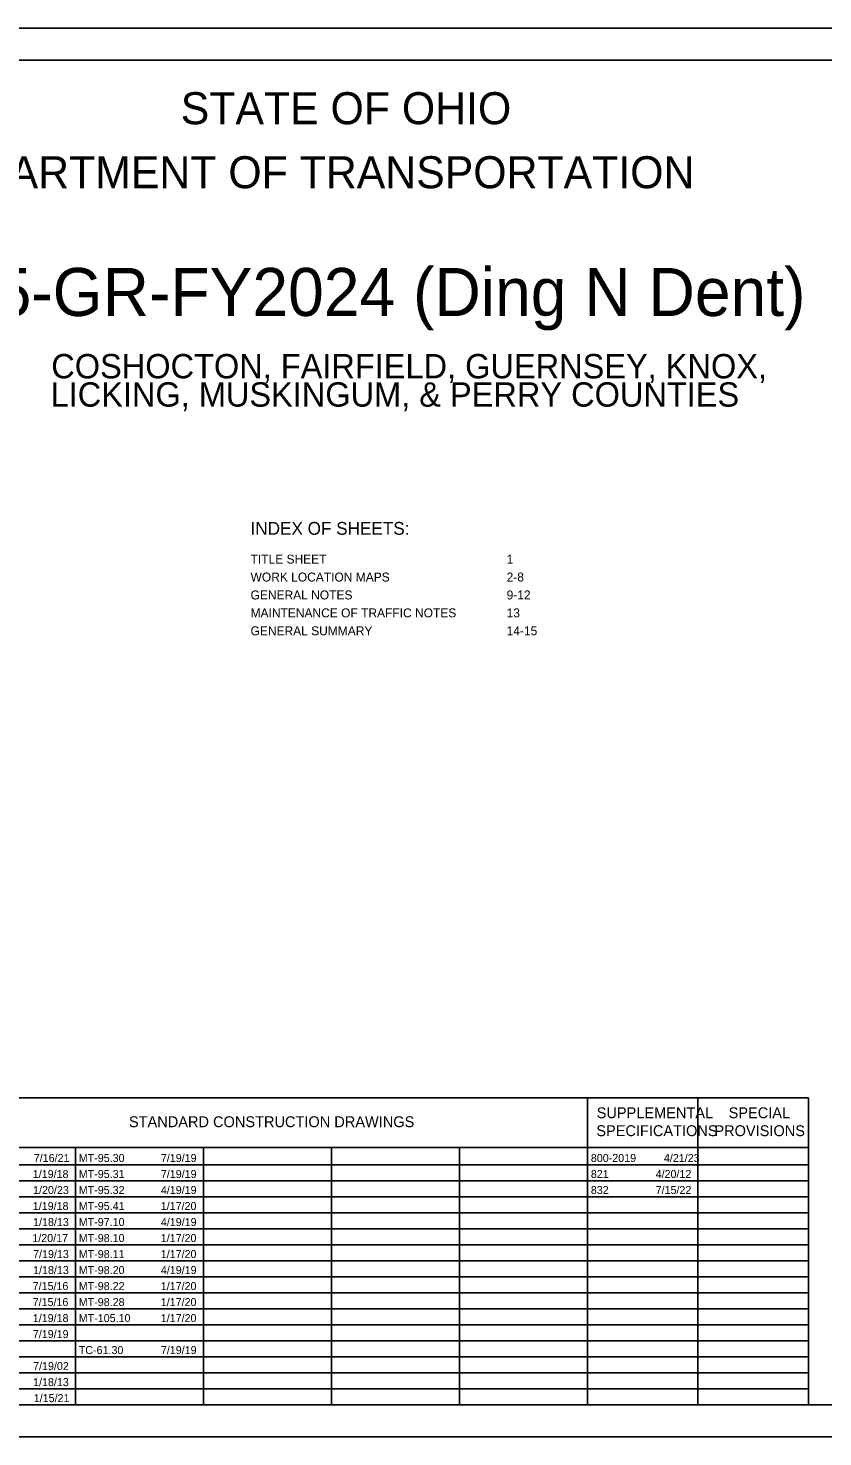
# Model space of a CAD drawing. Extents: x 0 to 34, y 0 to 22.
# Drawn here: x 11.41 to 23.83, y 0 to 22 of the extents above; entities that cross this region are included whole.
import ezdxf

# ---------------------------------------------------------------- set-up
doc = ezdxf.new("R2010")
doc.units = 0
for name, color, linetype in [('Default', 7, 'Continuous'), ('SH_Border', 7, 'Continuous'), ('SH_Cut_Line', 7, 'Continuous'), ('SH_Data', 7, 'Continuous'), ('SH_Text', 7, 'Continuous')]:
    doc.layers.add(name, color=color, linetype=linetype)

msp = doc.modelspace()

# ---------------------------------------------------------------- linework, layer by layer
at = {"layer": 'SH_Border'}
msp.add_lwpolyline([(1.5, 21.5), (33.5, 21.5), (33.5, 0.5), (1.5, 0.5)], close=True, dxfattribs=at)
at = {"layer": 'SH_Cut_Line'}
msp.add_lwpolyline([(0, 0), (34, 0), (34, 22), (0, 22)], close=True, dxfattribs=at)
at = {"layer": 'SH_Data'}
for p, q in [((10.15, 5.292), (23.6, 5.292)), ((20.15, 0.5), (20.15, 5.292)), ((21.875, 0.5), (21.875, 5.292)), ((23.6, 0.5), (23.6, 5.292)), ((10.15, 4.521), (23.6, 4.521)), ((12.15, 0.5), (12.15, 4.521)), ((14.15, 0.5), (14.15, 4.521)), ((16.15, 0.5), (16.15, 4.521)), ((18.15, 0.5), (18.15, 4.521)), ((10.15, 4.25), (23.6, 4.25)), ((10.15, 4), (23.6, 4)), ((10.15, 3.75), (23.6, 3.75)), ((10.15, 3.5), (23.6, 3.5)), ((10.15, 3.25), (23.6, 3.25)), ((10.15, 3), (23.6, 3)), ((10.15, 2.75), (23.6, 2.75)), ((10.15, 2.5), (23.6, 2.5)), ((10.15, 2.25), (23.6, 2.25)), ((10.15, 2), (23.6, 2)), ((10.15, 1.75), (23.6, 1.75)), ((10.15, 1.5), (23.6, 1.5)), ((10.15, 1.25), (23.6, 1.25)), ((10.15, 1), (23.6, 1)), ((10.15, 0.75), (23.6, 0.75))]:
    msp.add_line(p, q, dxfattribs=at)

# ---------------------------------------------------------------- texts
at = {"layer": 'Default'}
for s, p in [('7/16/21', (11.499, 4.292)), ('MT-95.30', (12.202, 4.292)), ('7/19/19', (13.485, 4.292)), ('800-2019', (20.202, 4.292)), ('4/21/23', (21.343, 4.292)), ('1/19/18', (11.484, 4.042)), ('MT-95.31', (12.202, 4.042)), ('7/19/19', (13.485, 4.042)), ('821', (20.202, 4.042)), ('4/20/12', (21.214, 4.042)), ('1/20/23', (11.489, 3.792)), ('MT-95.32', (12.202, 3.792)), ('4/19/19', (13.485, 3.792)), ('832', (20.202, 3.792)), ('7/15/22', (21.214, 3.792)), ('1/19/18', (11.484, 3.542)), ('MT-95.41', (12.202, 3.542)), ('1/17/20', (13.483, 3.542)), ('1/18/13', (11.489, 3.292)), ('MT-97.10', (12.202, 3.292)), ('4/19/19', (13.485, 3.292)), ('1/20/17', (11.477, 3.042)), ('MT-98.10', (12.202, 3.042)), ('1/17/20', (13.483, 3.042)), ('7/19/13', (11.489, 2.792)), ('MT-98.11', (12.202, 2.792)), ('1/17/20', (13.483, 2.792)), ('1/18/13', (11.489, 2.542)), ('MT-98.20', (12.202, 2.542)), ('4/19/19', (13.485, 2.542)), ('7/15/16', (11.482, 2.292)), ('1/17/20', (13.483, 2.292)), ('MT-98.22', (12.202, 2.292)), ('7/15/16', (11.482, 2.042)), ('MT-98.28', (12.202, 2.042)), ('1/17/20', (13.483, 2.042)), ('1/19/18', (11.484, 1.792)), ('MT-105.10', (12.202, 1.792)), ('1/17/20', (13.483, 1.792)), ('7/19/19', (11.485, 1.542)), ('TC-61.30', (12.202, 1.292)), ('7/19/19', (13.485, 1.292)), ('7/19/02', (11.489, 1.042)), ('1/18/13', (11.489, 0.792)), ('1/15/21', (11.499, 0.542))]:
    msp.add_text(s, height=0.125, dxfattribs=at).set_placement(p)
at = {"layer": 'SH_Text'}
for s, height, p in [('STATE OF OHIO', 0.5, (13.795, 20.5)), ('DEPARTMENT OF TRANSPORTATION', 0.5, (9.747, 19.5)), ('D05-GR-FY2024 (Ding N Dent)', 0.75, (9.621, 17.505)), ('COSHOCTON, FAIRFIELD, GUERNSEY, KNOX,', 0.38, (11.773, 16.531)), ('LICKING, MUSKINGUM, & PERRY COUNTIES', 0.38, (11.762, 16.089)), ('INDEX OF SHEETS:', 0.2, (14.886, 14.088)), ('TITLE SHEET', 0.14, (14.886, 13.638)), ('1', 0.14, (18.886, 13.638)), ('WORK LOCATION MAPS', 0.14, (14.886, 13.358)), ('2-8', 0.14, (18.886, 13.358)), ('GENERAL NOTES', 0.14, (14.886, 13.078)), ('9-12', 0.14, (18.886, 13.078)), ('MAINTENANCE OF TRAFFIC NOTES', 0.14, (14.886, 12.798)), ('13', 0.14, (18.886, 12.798)), ('GENERAL SUMMARY', 0.14, (14.886, 12.518)), ('14-15', 0.14, (18.886, 12.518)), ('SUPPLEMENTAL', 0.17, (20.293, 4.976)), ('SPECIAL', 0.17, (22.354, 4.976)), ('STANDARD CONSTRUCTION DRAWINGS', 0.17, (12.986, 4.836)), ('SPECIFICATIONS', 0.17, (20.287, 4.696)), ('PROVISIONS', 0.17, (22.132, 4.696))]:
    msp.add_text(s, height=height, dxfattribs=at).set_placement(p)

doc.saveas('drawing.dxf')
